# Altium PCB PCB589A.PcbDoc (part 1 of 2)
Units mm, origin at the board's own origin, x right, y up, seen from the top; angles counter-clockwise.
Board outline 111 x 86 mm, 2 copper layers (Top Layer, Top, Bottom Layer, Bottom); 127 components, 84 nets, 406 pads, 157 vias.
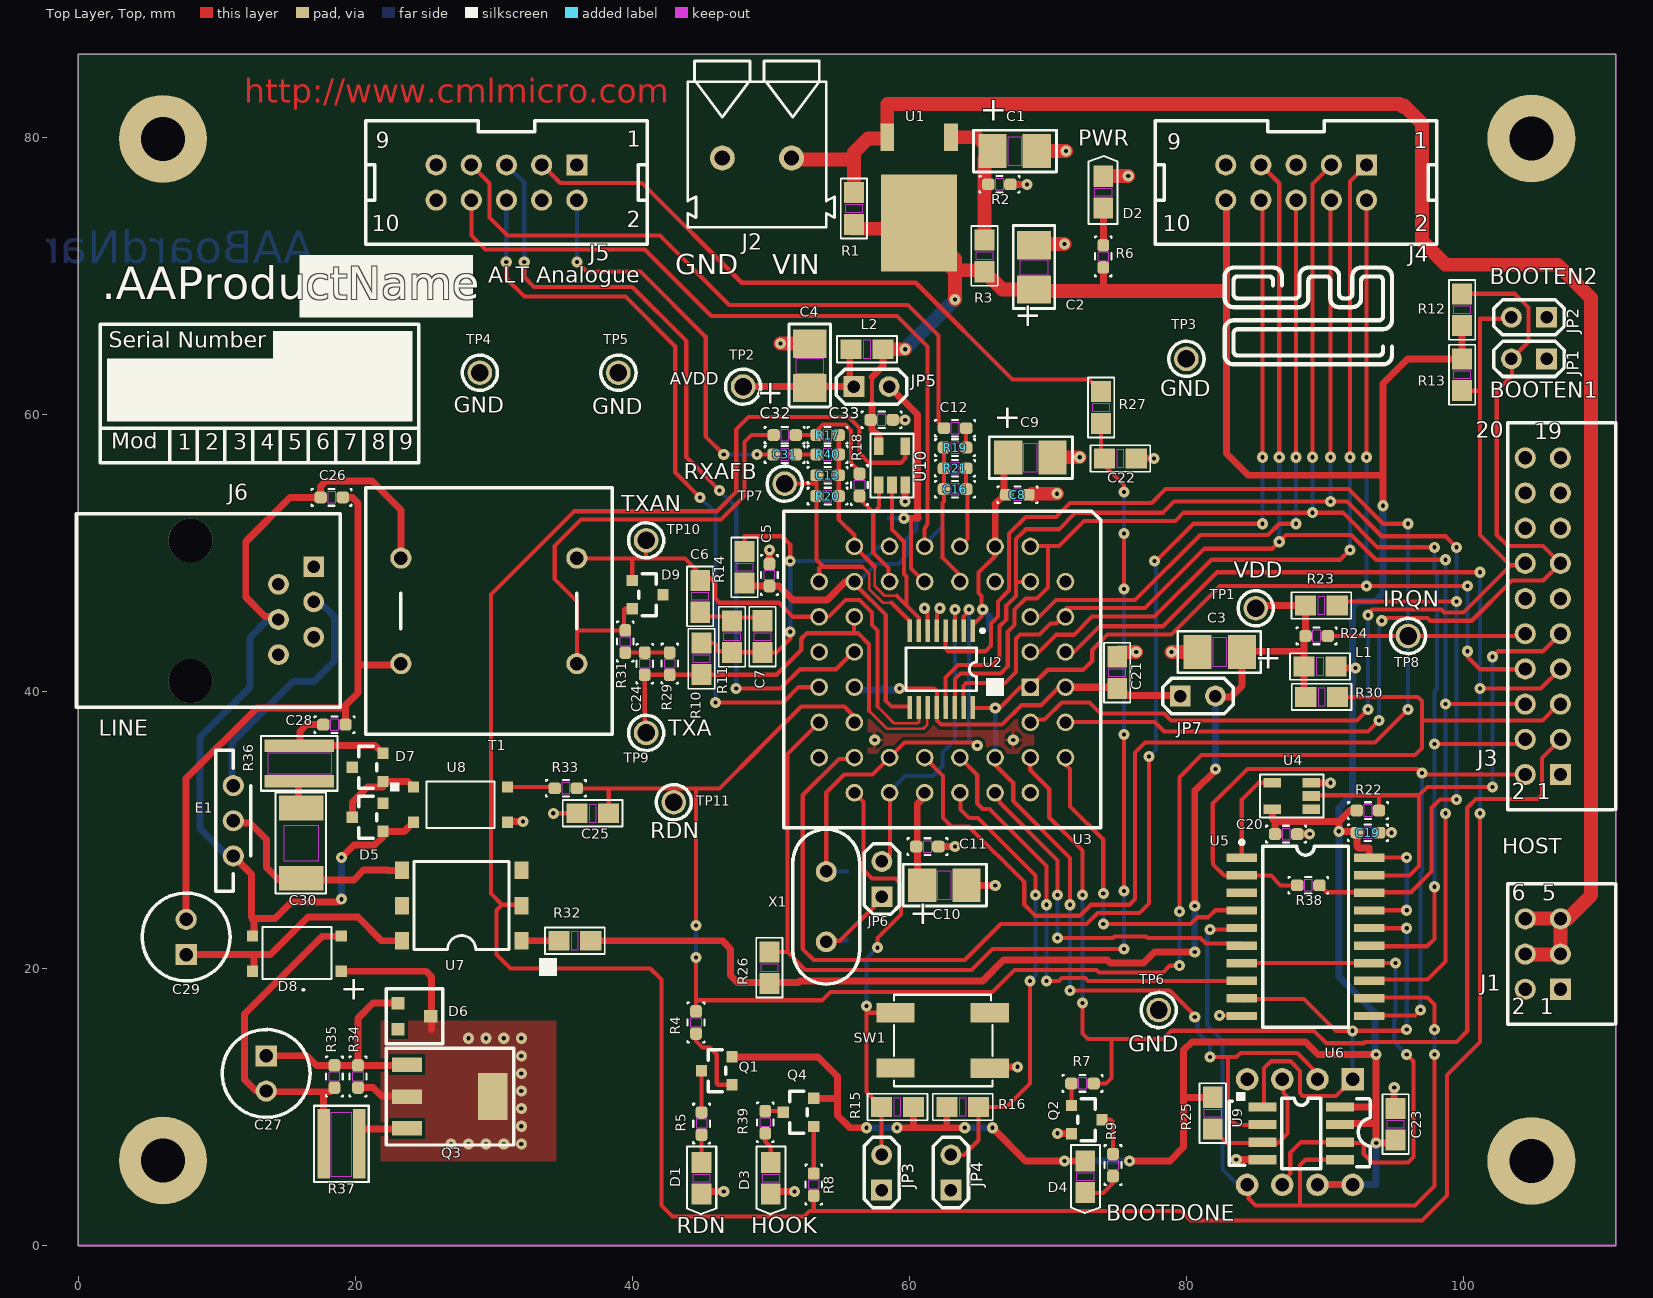
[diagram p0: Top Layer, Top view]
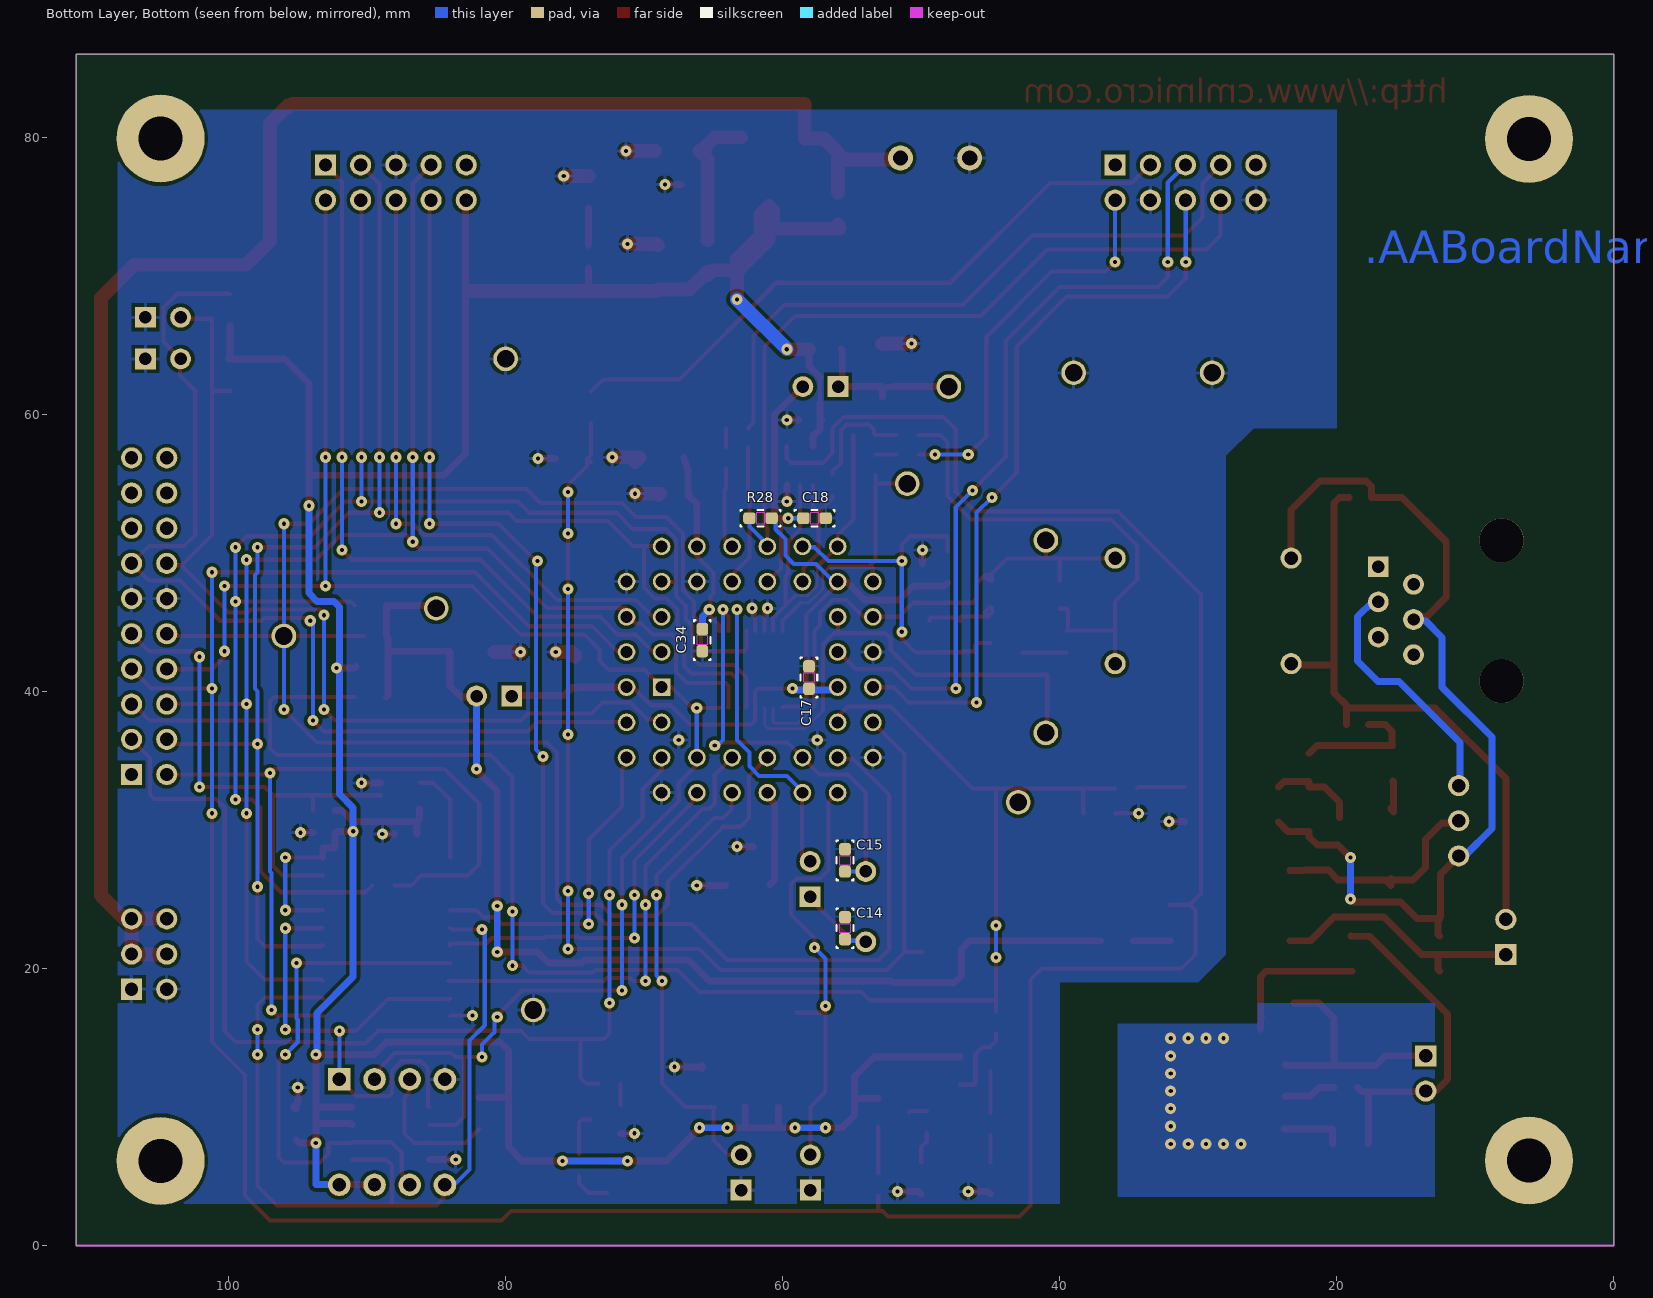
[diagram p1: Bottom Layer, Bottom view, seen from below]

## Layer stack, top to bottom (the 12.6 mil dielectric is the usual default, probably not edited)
Top Layer, Top: signal copper 0.0356
Dielectric: dielectric 0.32, FR-4, Dk 4.8
Bottom Layer, Bottom: signal copper 0.0356

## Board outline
0,0 111,0 111,86 0,86

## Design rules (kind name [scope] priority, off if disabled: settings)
Clearance Clearance_Polygon [InPolygon] p1: gap=0.25
Clearance Clearance_NetClass(LINESIDE)-NetClass(EQPTSIDE-AN) [InNetClass('LINESIDE') vs InNetClass('EQPTSIDE-AN')] p2: gap=2.5
Clearance Clearance_NetClass(LINESIDE)-NetClass(EQPTSIDE-DIG) [InNetClass('LINESIDE') vs InNetClass('EQPTSIDE-DIG')] p3: gap=2.5
Clearance Clearance_NetClass(LINESIDE) [InNetClass('LINESIDE') vs not IsKeepOut] p4: gap=0.5
Clearance Clearance_Keepout_NetClass(LINESIDE) [InNetClass('LINESIDE') vs IsKeepOut] p5: gap=0.01
Clearance "Clearance_Cu, PadToPad" [OnCopper And IsPad vs OnCopper And IsPad] p6: gap=0.2
Clearance "Clearance_Cu PadToLine" [OnCopper And IsPad vs OnCopper And IsWire] p7: gap=0.2
Clearance "Clearance_Cu, LineToLine" [OnCopper And IsWire vs OnCopper And IsWire] p8: gap=0.2
Clearance "Clearance_Cu, ViaToPad" [OnCopper And IsVia vs OnCopper And IsPad] p9: gap=0.2
Clearance "Clearance_Cu, ViaToLine" [OnCopper And IsVia vs OnCopper And IsWire] p10: gap=0.2
Clearance "Clearance_Cu, ViaToVia" [OnCopper And IsVia vs OnCopper And IsVia] p11: gap=0.2
ComponentClearance [All] p1 off: gap=0.254 collisioncheckmode=3 verticalgap=0.254 showdistances=FALSE
Height [All] p1 off: minheight=0 maxheight=25.4 prefheight=12.7
HoleSize [All] p1: absolutevalues=TRUE maxlimit=4 minlimit=0.2 maxpercent=80.000 minpercent=20.000
MinimumSolderMaskSliver [All] p1: minsoldermaskwidth=0.1
PlaneClearance [All] p1: clearance=0.254
PolygonConnect PolygonConnect_11 [All vs IsNamedPolygon('Top Layer, Top-LNET320') Or  IsNamedPolygon('Bottom Layer, Bottom-LNET320')] p1: connectstyle=Direct reliefconductorwidth=0.254 reliefentries=4 polygonreliefangle="90 Angle"
PolygonConnect PolygonConnect_10 [All vs IsNamedPolygon('Bottom Layer, Bottom-GND')] p2: connectstyle=Relief reliefconductorwidth=0.254 reliefentries=4 polygonreliefangle="90 Angle"
PolygonConnect PolygonConnect_9 [All vs IsNamedPolygon('Bottom Layer, Bottom-LNET320')] p3: connectstyle=Direct reliefconductorwidth=0.254 reliefentries=4 polygonreliefangle="90 Angle"
PolygonConnect PolygonConnect_8 [All vs IsNamedPolygon('Top Layer, Top-LNET320')] p4: connectstyle=Direct reliefconductorwidth=0.254 reliefentries=4 polygonreliefangle="90 Angle"
PolygonConnect PolygonConnect_7 [All vs IsNamedPolygon('Top Layer, Top-LNET320')] p5: connectstyle=Direct reliefconductorwidth=0.254 reliefentries=4 polygonreliefangle="90 Angle"
PolygonConnect PolygonConnect_6 [IsPolygon And InNet('GND') And OnLayer('Bottom Layer, Bottom') vs IsVia] p6: connectstyle=Relief reliefconductorwidth=0.381 reliefentries=4 polygonreliefangle="45 Angle"
PolygonConnect PolygonConnect_5 [IsPolygon And InNet('GND') And OnLayer('Bottom Layer, Bottom') vs IsPad] p7: connectstyle=Relief reliefconductorwidth=0.381 reliefentries=4 polygonreliefangle="45 Angle"
PolygonConnect PolygonConnect_4 [IsPolygon And InNet('LNET320') And OnLayer('Bottom Layer, Bottom') vs IsVia] p8: connectstyle=Direct reliefconductorwidth=0.381 reliefentries=4 polygonreliefangle="90 Angle"
PolygonConnect PolygonConnect_3 [IsPolygon And InNet('LNET320') And OnLayer('Bottom Layer, Bottom') vs IsPad] p9: connectstyle=Direct reliefconductorwidth=0.381 reliefentries=4 polygonreliefangle="90 Angle"
PolygonConnect PolygonConnect_2 [IsPolygon And InNet('LNET320') And OnLayer('Top Layer, Top') vs IsVia] p10: connectstyle=Direct reliefconductorwidth=0.381 reliefentries=4 polygonreliefangle="90 Angle"
PolygonConnect PolygonConnect_1 [IsPolygon And InNet('LNET320') And OnLayer('Top Layer, Top') vs IsPad] p11: connectstyle=Direct reliefconductorwidth=0.381 reliefentries=4 polygonreliefangle="90 Angle"
PolygonConnect [All] p12: connectstyle=Relief reliefconductorwidth=0.254 reliefentries=4 polygonreliefangle="90 Angle"
RoutingVias [All] p1: holewidth=0.5 width=1 viastyle="Through Hole" minholewidth=0.3 minwidth=0.8 maxholewidth=0.6 maxwidth=1.2
SilkToSilkClearance [All] p1: silktosilkclearance=0.15
SilkscreenOverComponentPads [All] p1: minsilkscreentomaskgap=0.1
SolderMaskExpansion [All] p1 off: expansion=0.102
UnConnectedPin [All] p1:
Width Width_LineSide [InNetClass('LINESIDE')] p1: maxlimit=0.505 minlimit=0.495 preferedwidth=0.5 minimp=50.000000 maximp=50.000000 favimp=50.000000
Width [All] p2: maxlimit=1 minlimit=0.2 preferedwidth=0.3 minimp=50.000000 maximp=50.000000 favimp=50.000000
21 further rules are at their usual default settings.

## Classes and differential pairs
net class EQPTSIDE-DIG: BOOTDONE BOOTEN1 BOOTEN2 C.CSN C.CTSN C.DCDN C.DSRN C.DVDDI C.VDD CDATA CSN EP.EPCSN EP.EPSCLK EP.EPSI EP.WPN EPCSN EPSCLK EPSI EVAL EXTLINK45 GND HDN IRQN MEMPROGN NET00000 NET00002 NET00004 NET00005 NET00006 NetC1_A NetC10_A NetC14_2 NetD1_1 NetD2_1 NetD3_1 NetQ1_1 NetQ1_3 NetQ4_1 NetQ4_3 NetR32_2 NetR33_2 RDATA RDN RLYDRV SCLK VDD VDEC VIN XTAL XTALN
net class EQPTSIDE-AN: C.AVDD C.AVDD.I NET00027 NET00028 NET00155 NET00156 NET00157 NetC24_2 NetC31_1 NetC32_2 RXA RXAFB RXAIN RXALT RXAN RXB RXBIN TXA TXAN TXB TXBN VBIAS
net class LINESIDE: NetC26_1 NetC26_2 NetC27_1 NetC27_2 NetC28_2 NetC29_2 NetC30_1 NetC30_2 NetD5_3 NetD6_3 NetE1_1 NetQ3_3

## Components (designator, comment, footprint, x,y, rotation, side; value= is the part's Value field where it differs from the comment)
C1 "n/f" TC3528P_CAP_TANT_TAJ_B(Primary) 66,79 r0 top
C2 "10uF(16V)" TC3528P_CAP_TANT_TAJ_B(Primary) 69,69 r90 top
C3 "10uF(16V)" TC3528P_CAP_TANT_TAJ_B(Primary) 84,42.84 r180 top
C4 "10uF(16V)" TC3528P_CAP_TANT_TAJ_B(Primary) 52.805,61.89 r90 top
C5 "100nF" 0603COM#1 49.9,49.2 r90 top
C6 "nf" CC0805 44.9,48 r270 top
C7 "nf" CC0805 49.4,45.1 r270 top
C8 "1uF" 0603COM#1 68.6,54.2 r0 top
C9 "10uF" TC3528P_CAP_TANT_TAJ_B(Primary) 67.14,56.874 r0 top
C10 "10uF" TC3528P_CAP_TANT_TAJ_B(Primary) 60.93,26.014 r0 top
C11 "100nF" 0603COM#1 62.1,28.8 r0 top
C12 "100nF" 0603COM#1 64.1,59 r0 top
C13 "220pF" 0603COM#2 54.9,55.6 r0 top
C14 "47pF" 0603COM#2 55.5,23.7 r90 bottom
C15 "47pF" 0603COM#2 55.5,28.6 r90 bottom
C16 "100pF" 0603COM#2 64.1,54.6 r0 top
C17 "100nF" 0603COM#2 58.1,41.8 r90 bottom
C18 "100nF" 0603COM#2 58.5,52.5 r0 bottom
C19 "10nF" 0603COM#2 92.3,29.8 r180 top
C20 "10nF" 0603COM#2 86.4,29.7 r180 top
C21 "100nF" CC0805 75,42.5 r270 top
C22 "n/f" CC0805 76.38,56.81 r180 top
C23 "100nF" CC0805 95.1,9.9 r270 top
C24 "15nF" 0603COM#2 40.9,41.2 r270 top
C25 "330nF" CC0805 36,31.2 r0 top
C26 "33nF" 0603COM#2 17.5,54 r180 top
C27 "4u7F (100V)" CAP100R 13.575,13.69 r270 top
C28 "100nF" 0603COM#2 19.3,37.6 r0 top
C29 "4u7F (100V)" CAP100R 7.8,21 r90 top
C30 "0.33uF (250v)" CC1812 16,26.5 r90 top
C31 "100nF" 0603COM#1 51.8,57.1 r0 top
C32 "100nF" 0603COM#1 51.8,58.5 r0 top
C33 "100nF" 0603COM#1 58.8,59.6 r0 top
C34 "n/f" 0603COM#1 65.8,42.9 r270 bottom
D1 "RDN" LED0805 45,6 r270 top
D2 "PWR" LED0805 74,74.9 r90 top
D3 "HOOK" LED0805 50,6 r270 top
D4 "BOOTDONE" LED0805 72.7,6.1 r270 top
D5 "n/f" SOT23(SDG) 22,29.9 r90 top
D6 "8V2" SO-G3/Z3.3 23.1,17.5 r270 top
D7 "18v" SOT23(SDG) 22,33.5 r90 top
D8 "" SDIP4 19,19.8 r180 top
D9 "2V7" SOT23(SDG) 40,48 r270 top
E1 "TM2P-10271" TM2PRO 11.2,33.2 r180 top
J1 "" IDC6RM 107,18.5 r90 top locked
J2 "SCRWLESS2" SCRWLESS_2 46.5,78.5 r90 top
J3 "HOST" IDC20RM 107,34 r90 top locked
J4 "n/f" IDC10M 93,78 r0 top
J5 "ALT Analogue" IDC10M 36,78 r0 top
J6 "LINE" RJ11SKT_RJ11SKT(Primary) 17,49 r270 top
JP1 "BOOTEN1" JMP2 106,64 r180 top
JP2 "BOOTEN2" JMP2 106,67 r180 top
JP3 "EVAL" JMP2 58,4 r90 top
JP4 "EXTLINK45" JMP2 63,4 r90 top
JP5 "JUMPER2" JMP2 56,62 r0 top
JP6 "" JMP2 58.02,25.184 r90 top
JP7 "" JMP2 79.555,39.665 r0 top
L1 "100nH" RC0805 88.5,41.8 r0 top
L2 "100nH" RC0805 55.8,64.7 r0 top
Q1 "" SOT-23 47.2,11.6 r90 top
Q2 "" SOT23(SDG)_BC846(Primary) 71.7,10.1 r270 top
Q3 "" DSO-G3/D7 23.735,13.055 r270 top
Q4 "" SOT-23 53.1,8.6 r90 top
R1 "n/f" RC0805 56,76 r270 top
R2 "0R" 0603COM#1 67.3,76.6 r0 top
R3 "n/f" RC0805 65.425,72.575 r270 top
R4 "10k" 0603COM#2 44.6,16.9 r90 top
R5 "360R" 0603COM#2 45,8 r270 top
R6 "470R" 0603COM#2 74,72.2 r90 top
R7 "10k" 0603COM#2 73.3,11.7 r0 top
R8 "10k" 0603COM#2 53.1,3.6 r270 top
R9 "360R" 0603COM#2 74.7,6.6 r90 top
R10 "nf" RC0805 45,43.5 r270 top
R11 "nf" RC0805 47.2,42.8 r90 top
R12 "10k" RC0805 99.9,66.4 r90 top
R13 "10k" RC0805 99.9,64 r270 top
R14 "0R" RC0805 48.1,50.1 r270 top
R15 "10k" RC0805 58,10 r0 top
R16 "n/f" RC0805 65,10 r180 top
R17 "150K" 0603COM#2 53.3,58.5 r180 top
R18 "27k" 0603COM#1 56.4,55.7 r90 top
R19 "150K" 0603COM#1 64.1,57.6 r0 top
R20 "100K" 0603COM#1 54.9,54.1 r0 top
R21 "150K" 0603COM#1 62.5,56.1 r180 top
R22 "10k" 0603COM#2 93.9,31.4 r0 top
R23 "1M" RC0805 88.6,46.2 r0 top
R24 "100K" 0603COM#1 88.6,44 r180 top
R25 "10k" RC0805 81.9,10.7 r270 top
R26 "470K" RC0805 49.9,21.2 r270 top
R27 "n/f" RC0805 73.84,59.35 r90 top
R28 "0R" 0603COM#2 62.4,52.5 r0 bottom
R29 "510R" 0603COM#2 42.7,42.8 r90 top
R30 "470K" RC0805 90.9,39.6 r180 top
R31 "0R" 0603COM#1 39.5,44.4 r90 top
R32 "270R" RC0805 37,22 r180 top
R33 "100R" 0603COM#2 36,33 r0 top
R34 "33K" 0603COM#2 20.2,13 r90 top
R35 "27K" 0603COM#2 18.5,13 r90 top
R36 "10k (0.5W)" RC12181WA 16,36 r270 top
R37 "22R (1W)" RC12181WA 20.2,7.3 r180 top
R38 "n/f" 0603COM#2 88,26 r180 top
R39 "360R" 0603COM#2 49.6,8.1 r270 top
R40 "150K" 0603COM#1 53.3,57.1 r180 top
SW1 "n/f" OMRONB3SN 59,16.8 r270 top
T1 "P5100" LINEXFMR_XFMR_LINE(Primary) 36,42 r180 top
TP1 "VDD" FISH_BEAD_FOOT_FISH_BEAD(Primary) 85,46 r270 top
TP2 "AVDD" FISH_BEAD_FOOT_FISH_BEAD(Primary) 48,62 r270 top
TP3 "GND" FISH_BEAD_FOOT_FISH_BEAD(Primary) 80,64 r0 top
TP4 "GND" FISH_BEAD_FOOT_FISH_BEAD(Primary) 29,63 r0 top
TP5 "GND" FISH_BEAD_FOOT_FISH_BEAD(Primary) 39,63 r0 top
TP6 "GND" FISH_BEAD_FOOT_FISH_BEAD(Primary) 78,17 r0 top
TP7 "RXAFB" FISH_BEAD_FOOT_FISH_BEAD(Primary) 51,55 r180 top
TP8 "IRQN" FISH_BEAD_FOOT_FISH_BEAD(Primary) 96,44 r0 top
TP9 "TXA" FISH_BEAD_FOOT_FISH_BEAD(Primary) 41,37 r180 top
TP10 "TXAN" FISH_BEAD_FOOT_FISH_BEAD(Primary) 41,50.9 r180 top
TP11 "RDN" FISH_BEAD_FOOT_FISH_BEAD(Primary) 43,32 r180 top
U1 "" TO-252 63,80 r180 top
U2 "CMX865AE4" E4 62.3,41.6 r180 top
U3 "" PLCCSOCKET44 68.73,40.304 r180 top
U4 "" SOT23-5 89,31.5 r90 top
U5 "" SO-G20 84,28 r0 top
U6 "" DIP8 92,12 r270 top
U7 "" SMD6 32,22 r180 top
U8 "" SOP4 24.2,33.1 r0 top
U9 "n/f" SO8 85.5,10 r0 top
U10 "TS12A4514DBVR" SOT23-5 57.8,54.9 r0 top
X1 "6.1440MHz" HC49 54,27 r270 top

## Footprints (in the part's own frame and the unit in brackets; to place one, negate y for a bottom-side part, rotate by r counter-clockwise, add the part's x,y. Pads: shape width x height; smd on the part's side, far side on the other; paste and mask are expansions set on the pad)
0603COM#1 [mm]
  rrect50% 0.9x0.85 smd: 1(0,0) 2(-1.6,0)
  Top Layer, Top keep-out region: -1.1,-0.4 -0.5,-0.4 -0.5,0.4 -1.1,0.4
  silkscreen extent -2.23,-0.6 0.64,0.6
0603COM#2 [mm]
  rrect50% 0.9x0.85 smd: 1(0,0) 2(-1.6,0)
  Top Layer, Top pour cut-out: -0.05,0.65 -1.55,0.65 -1.55,-0.65 -0.05,-0.65
  Top Layer, Top keep-out region: -1.1,-0.4 -0.5,-0.4 -0.5,0.4 -1.1,0.4
  silkscreen extent -2.23,-0.6 0.64,0.6
CAP100R [mil]
  round 60 hole 38: 1(100,0)
  rect 60x60 hole 38: 2(0,0)
  silkscreen extent -75,-125 175,125
CC0805 [mil]
  rect 60x56 smd: 1(0,0) 2(90,0)
  Top Layer, Top keep-out region: 55,-25 55,25 35,25 35,-25
  silkscreen extent -40,-38 130,38
CC1812 [mil]
  rect 70x126 smd: 1(0,-3.94) 2(200,-3.94)
  Top Layer, Top keep-out region: 150,-53.94 150,46.06 50,46.06 50,-53.94
  silkscreen extent -43,-75 244,69
DIP8 [mil]
  rect 64x64 hole 38: 1(0,0)
  round 64 hole 38: 2(0,-100) 3(0,-200) 4(0,-300) 5(300,-300) 6(300,-200) 7(300,-100) 8(300,0)
  silkscreen extent 60,-350 244,50
DSO-G3/D7 [mm]
  rect 1.05x2.15 smd: 1(0,0) 2(2.3,0) 3(4.6,0)
  rect 3.4x2.15 smd: 4(2.3,6.2)
  silkscreen extent -1.2,-1.5 5.8,7.7
E4 [mm]
  rect 0.3x1.65 smd: 1(-2.275,-2.775) 2(-1.625,-2.775) 3(-0.975,-2.775) 4(-0.325,-2.775) 5(0.325,-2.775) 6(0.975,-2.775) 7(1.625,-2.775) 8(2.275,-2.775) 9(2.275,2.775) 10(1.625,2.775) 11(0.975,2.775) 12(0.325,2.775) 13(-0.325,2.775) 14(-0.975,2.775) 15(-1.625,2.775) 16(-2.275,2.775)
  silkscreen extent -3.1,-2.9 2.55,1.55
FISH_BEAD_FOOT_FISH_BEAD(Primary) [mil]
  round 70 hole 50: TP(0,0)
  silkscreen extent -50,-50 50,50
HC49 [mm]
  round 1.5 hole 0.9: 1(0,0) 2(5.08,0)
  silkscreen extent -3.05,-2.41 8.13,2.41
IDC6RM [mil]
  rect 60x60 hole 38: 1(0,0)
  round 60 hole 38: 2(0,100) 3(100,0) 4(100,100) 5(200,0) 6(200,100)
  silkscreen extent -100,-157 300,150
IDC10M [mil]
  rect 60x60 hole 38: 1(0,0)
  round 60 hole 38: 2(0,-100) 3(-100,0) 4(-100,-100) 5(-200,0) 6(-200,-100) 7(-300,0) 8(-300,-100) 9(-400,0) 10(-400,-100)
  silkscreen extent -600,-225 200,125
IDC20RM [mil]
  rect 60x60 hole 38: 1(0,0)
  round 60 hole 38: 2(0,100) 3(100,0) 4(100,100) 5(200,0) 6(200,100) 7(300,0) 8(300,100) 9(400,0) 10(400,100) 11(500,0) 12(500,100) 13(600,0) 14(600,100) 15(700,0) 16(700,100) 17(800,0) 18(800,100) 19(900,0) 20(900,100)
  silkscreen extent -100,-157 1000,150
JMP2 [mm]
  rect 1.5x1.5 hole 0.9: 1(0,0)
  round 1.5 hole 0.9: 2(2.54,0)
  silkscreen extent -1.27,-1.27 3.81,1.27
LED0805 [mil]
  rect 60x56 smd: 1(0,0) 2(90,0)
  Top Layer, Top keep-out region: 55,-25 55,25 35,25 35,-25
  silkscreen extent -46,-41 147,42
LINEXFMR_XFMR_LINE(Primary) [mil]
  round 60 hole 38: 1(0,0) 3(0,-300) 4(500,0) 6(500,-300)
  silkscreen extent -100,-500 600,200
OMRONB3SN [mm]
  rect 1.4x2.75 smd: 1(0,0) 2(3.988,0) 3(0,6.807) 4(4.013,6.807)
  silkscreen extent -1.3,-0.1 5.3,7
PLCCSOCKET44 [mil]
  rect 50x50 hole 34: 1(0,0)
  round 50 hole 34: 2(-100,-100) 3(0,-100) 4(-100,-200) 5(0,-200) 6(-100,-300) 7(0,-400) 8(0,-300) 9(100,-400) 10(100,-300) 11(200,-400) 12(200,-300) 13(300,-400) 14(300,-300) 15(400,-400) 16(400,-300) 17(500,-400) 18(600,-300) 19(500,-300) 20(600,-200) 21(500,-200) 22(600,-100) 23(500,-100) 24(600,0) 25(500,0) 26(600,100) 27(500,100) 28(600,200) 29(500,300) 30(500,200) 31(400,300) 32(400,200) 33(300,300) 34(300,200) 35(200,300) 36(200,200) 37(100,300) 38(100,200) 39(0,300) 40(-100,200) 41(0,200) 42(-100,100) 43(0,100) 44(-100,0)
  silkscreen extent -200,-500 700,400
RC0805 [mil]
  rect 60x56 smd: 1(0,0) 2(90,0)
  Top Layer, Top keep-out region: 55,-25 55,25 35,25 35,-25
  silkscreen extent -40,-38 130,38
RC12181WA [mm]
  rect 0.9x5 smd: 1(-0.08,-0.04) 2(2.47,-0.04)
  Top Layer, Top keep-out region: 1.95,-2.3 1.95,2.3 0.45,2.3 0.45,-2.3
  silkscreen extent -0.78,-2.79 3.17,2.71
RJ11SKT_RJ11SKT(Primary) [mm]
  rect 1.5x1.5 hole 0.9: 1(0,0)
  round 1.5 hole 0.9: 2(1.27,-2.54) 3(2.54,0) 4(3.81,-2.54) 5(5.08,0) 6(6.35,-2.54)
  round 3.175 hole 3.175: dummy1(8.255,-8.89) dummy2(-1.905,-8.89)
  silkscreen extent -3.81,-17.14 10.16,1.91
SCRWLESS_2 [mm]
  round 1.8 hole 1.1: 1(0,0) 2(0,-5)
  silkscreen extent -5,-8.1 7,2.5
SDIP4 [mil]
  rect 32x32 smd: 1(0.39,0) 2(0.39,-100) 3(252.36,-100) 4(252.36,0)
  silkscreen extent 28,-126 224,53
SMD6 [mil]
  rect 40x50 smd: 1(0,0) 2(0,-100) 3(0,-200) 4(340,-200) 5(340,-100) 6(340,0)
  silkscreen extent -100,-225 305,100
SO8 [mil]
  rect 80x26 smd: 1(0,0) 2(0,-50) 3(0,-100) 4(0,-150) 5(220,-150) 6(220,-100) 7(220,-50) 8(220,0)
  silkscreen extent -75,-175 165,42
SO-G3/Z3.3 [mm]
  rect 0.9x0.95 smd: 1(0,0) 2(1.9,0) 3(0.95,2.35)
  silkscreen extent -1.05,-0.87 2.95,3.23
SO-G20 [mm]
  rect 2.2x0.6 smd: 1(0,0) 2(0,-1.27) 3(0,-2.54) 4(0,-3.81) 5(0,-5.08) 6(0,-6.35) 7(0,-7.62) 8(0,-8.89) 9(0,-10.16) 10(0,-11.43) 11(9.2,-11.43) 12(9.2,-10.16) 13(9.2,-8.89) 14(9.2,-7.62) 15(9.2,-6.35) 16(9.2,-5.08) 17(9.2,-3.81) 18(9.2,-2.54) 19(9.2,-1.27) 20(9.2,0)
  silkscreen extent -0.15,-12.24 7.7,1.25
SOP4 [mil]
  rect 32x32 smd: 1(0,0) 2(0,-100) 3(267.72,-100) 4(267.72,0)
  silkscreen extent -65,-116 230,16
SOT23(SDG) [mil]
  rect 32x32 smd: 1(0,0) 2(80,0) 3(40,87)
  silkscreen extent -20,18 100,68
SOT23(SDG)_BC846(Primary) [mil]
  rect 32x32 smd: B(0,0) C(40,87) E(80,0)
  silkscreen extent -20,18 100,68
SOT23-5 [mm]
  rect 0.7x1.25 smd: 1(0,0) 2(0.95,0) 3(1.9,0) 4(1.9,2.8) 5(0,2.8)
  silkscreen extent -0.6,-0.9 2.5,3.7
SOT-23 [mil]
  rect 32x32 smd: 1(0,0) 2(80,0) 3(40,87)
  silkscreen extent -20,18 100,68
TC3528P_CAP_TANT_TAJ_B(Primary) [mil]
  rect 80x96 smd: A(0,0) B(126,0)
  Top Layer, Top keep-out region: 83,-40 83,40 43,40 43,-40
  silkscreen extent -54,-59 182,59
TM2PRO [mil]
  round 60 hole 38: 1(0,0) 2(0,100) 3(0,200)
  silkscreen extent -50,-100 50,300
TO-252 [mm]
  rect 1x2 smd: 1(0,0) 3(4.6,0)
  rect 5.5x7 smd: 2(2.3,6.2)

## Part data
C1 C2 C3 C4 C9 C10: library part CAP_TANT_TAJ_B, "TAJ series case code B, SMT tantalum"
C5 C8 C11 C12 C13 C14 C15 C16 C17 C18 C19 C20 C24 C26 C28 C31 C32 C33 C34: library part CAP0603, "SMT capacitor"
C6 C7 C21 C22 C23 C25: library part CAP0805, "SMT capacitor"
C27 C29: library part CAP100R, "Non-polarised radial capacitor 100 thou pin spacing."
C30: library part CAP1812, "Generic capacitor, surface mount 1812"
D1 D2 D3 D4: library part LED0805, "LED, 0805 surface mount"
D5: library part BAS16, "Switching diode, surface mount SOT-23"
D6: library part BZX84, "BZX series zener 300mW SMT"
D7 D9: library part CMPZDA, "Dual Zener diode, common anode, SOT-23"
D8: library part CBRHD-02, "Central Semiconductor surface mount bridge rectifier, 0.5A"
E1: library part TM2PRO, "2Pro Integrated overcurrent/overvoltage protection device"
J1: library part HEADER_2*3RM, "3 + 3 double row 0.1in header right angle"
J2: "2-way Screwless Terminal Block"
J3: library part HEADER_2*10RM, "10 + 10 double row 0.1in header right angle"
J4 J5: library part HEADER_2*5, "10 way, 0.1inch pitch header"
J6: library part RJ11SKT, "RJ11 telephone socket"
JP1 JP2 JP3 JP4 JP6 JP7: library part JUMPER2, "PIN HEADER 2X1"
JP5: "PIN HEADER 2X1"
L1 L2: library part IND0805, "SMT Inductor"
Q1 Q4: library part BC856, "General purpose transistor PNP SMT"
Q2: library part BC846, "NPN general purpose transistor"
Q3: library part CZT2000, "NPN Darlington 2W SOT223"
R1 R3 R10 R11 R12 R13 R14 R15 R16 R25: library part CRG0805, "Generic SMT resistor, 1%.0.125W."
R2 R4 R5 R6 R7 R8 R9 R17 R18 R19 R20 R21 R22 R24 R28 R29 R31 R33 R34 R35 R38 R39 R40: library part CRG0603, "Generic SMT resistor, 1%.0.1W."
R23 R30 R32: library part CRG0805, "Generic SMT resistor, 1%.0.125W, RS CRG0805 series."
R26 R27: library part CRG0805, "Generic SMT resistor, 1%.0.125W, 0805 series."
R36 R37: library part RC12181W, "Philips Components 1W, SMT 1218  resistor"
SW1: library part OMRONB3SN, "Omron B3SN series, low profile, SMT  tactile switch"
T1: library part XFMR_LINE, "600R line transformer"
TP1 TP2 TP3 TP4 TP5 TP6 TP7 TP8 TP9 TP10 TP11: library part FISH_BEAD, "Fish Beads 1.32mm PCB hole"
U1: library part LM1117-ADJ-TO-252
U2: "Telecom Signalling Device"
U3: library part PDSP2_CLCC44_J_SKT, "PDSP2 Platform for Telecoms"
U4: library part NC7SZ04M5, "Tiny Logic single Inverter"
U5: library part 74HC244_SOIC, "Octal buffer/line driver; 3-state"
U6: library part AT25HP512-10PI-2.7, "SPI Serial EEPROM 512k"
U7: library part LCA110S, "Single pole optoMOS relay"
U8: library part PC354NT, "AC input photocoupler"
U9: library part M25P10-AVMN, "SPI 1Mbit Flash low voltage"
U10: "TI, SPST, CMOS analogue switch, surface mount SOT23-5"
X1: library part XTAL-HC49, "HC49 Xtal"

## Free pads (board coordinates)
  round 6.35 hole 3.175: 4(6.123,6.135) 4(6.123,79.883) 4(104.897,6.11) 4(104.897,79.91)

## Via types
v1: diameter 0.8, hole 0.3, Top Layer, Top to Bottom Layer, Bottom, tented both sides, 154 vias
v2: diameter 0.8, hole 0.3, Top Layer, Top to Bottom Layer, Bottom, 3 vias

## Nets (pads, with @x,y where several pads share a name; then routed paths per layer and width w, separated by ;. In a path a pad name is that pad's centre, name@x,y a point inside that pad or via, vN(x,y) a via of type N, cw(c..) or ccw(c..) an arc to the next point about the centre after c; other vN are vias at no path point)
BOOTDONE: J3.3 R7.1 U3.41 | length 81.1
  Top Layer, Top w0.3: U3.41@68.73,35.224 68.73,34.324 70.1,32.954 70.1,30.9 72.5,28.5 v1(72.5,25.3) ; v1(72.5,17.5) 72.5,15.3 72.9,14.9 74.6,14.9 ; R7.1@73.3,11.7 74.2,11.7 74.6,12.1 74.6,14.9 ; 99.5,14.7 99.482,14.7 ; J3.3@107,36.54 105.66,35.2 105.66,32.56 105.333,32.233 100.907,32.233 100.272,31.598 100.272,15.49 99.482,14.7 ; 74.6,14.9 78.3,14.9 78.9,15.5 89.2,15.5 90.1,14.6 92.8,14.6 92.9,14.7 99.482,14.7
  Bottom Layer, Bottom w0.3: v1(72.5,17.5) v1(72.5,25.3)
BOOTEN1: J3.13 JP1.2 R12.2 U3.42 | length 73.5
  Top Layer, Top w0.3: U3.42@71.27,37.764 71.29,37.784 77.716,37.784 78.4,37.1 93.1,37.1 v1(93.9,37.9) ; v1(94.1,45.1) 94.1,45.2 94.2,45.3 97.4,45.3 97.6,45.1 100.6,45.1 103.5,48 105.76,48 J3.13@107,49.24 105.74,50.5 103.2,50.5 102.4,51.3 102.4,61.7 103.5,62.8 103.5,64 JP1.2@103.46,64 104.7,65.24 104.7,67.7 103.7,68.7 100.1,68.7 R12.2@99.9,68.686
  Bottom Layer, Bottom w0.3: v1(93.9,37.9) 93.9,45 94,45 v1(94.1,45.1)
BOOTEN2: J3.14 JP2.2 R13.2 U3.43 | length 68.2
  Top Layer, Top w0.3: U3.43@68.73,37.764 68.93,37.964 69.764,37.964 71,39.2 73,39.2 73.8,38.4 78.4,38.4 78.9,37.9 92.3,37.9 v1(93.1,38.7) ; v1(93.1,45.5) 93,45.5 93.05,45.55 93.4,45.9 98.4,45.9 98.6,45.7 100,45.7 103.4,49.1 ; R13.2@99.9,61.714 99.9,61.7 101.2,61.7 ; JP2.2@103.46,67 103.36,66.9 101.2,66.9 101.2,61.7 ; J3.14@104.46,49.24 104.32,49.1 103.4,49.1 ; 101.2,61.7 101.2,51.3 103.4,49.1
  Bottom Layer, Bottom w0.3: v1(93.1,38.7) v1(93.1,45.5)
C.AVDD: C4.A JP5.1 L2.1 TP2.TP | length 11.4
  Top Layer, Top w0.5: TP2.TP@48,62 52,62 C4.A@52.805,61.89 ; C4.A@52.805,61.255 C4.A@52.805,61.89 ; L2.1@55.8,64.7 55.7,64.6 JP5.1@55.7,62 ; JP5.1@56,62 JP5.1@55.7,62 ; C4.A@52.805,61.89 52.915,62 JP5.1@55.7,62
C.AVDD.I: C18.1 JP5.2 U3.14 | length 18
  Top Layer, Top w0.3: v1@59.8,52.5 v1(59.6,52.5) 60,52.4 60.125,52.275 60.125,48.875 61,48 61.2,48 U3.14@61.11,47.924
  Top Layer, Top w0.5: JP5.2@58.54,62 60.6,60 60.6,52.5 v1@59.8,52.5
  Bottom Layer, Bottom w0.3: C18.1@58.5,52.5 v1(59.6,52.5)
C.CSN: J4.4 R23.2 R38.2 U2.13 U3.8 U5.18 | length 115.4
  Top Layer, Top w0.3: U2.13@62.625,38.825 62.6,38.85 62.6,41 63.5,41.9 66,41.9 66.5,42.4 66.5,44.7 67,45.2 67,46.2 67.7,46.9 67.7,47.9 ; U3.8@68.73,47.924 68.624,47.924 68.6,47.9 67.7,47.9 ; R38.2@89.6,26 90.1,25.5 93.2,25.5 U5.18@93.2,25.46 93.24,25.5 96.2,25.5 97.7,27 97.7,31.6 98.3,32.2 v1(99.5,32.2) ; v1(90.4,56.9) 90.4,75.4 J4.4@90.46,75.46 ; R23.2@90.886,46.2 90.986,46.3 91.186,46.5 v1(99.5,46.5) ; v1(99.5,50.4) 98.7,51.2 94.1,51.2 91.6,53.7 v1(90.4,53.7) 79.1,53.7 78.3,52.9 72,52.9 70.8,51.7 68.4,51.7 67.7,51 67.7,47.9
  Bottom Layer, Bottom w0.3: v1(90.4,53.7) v1(90.4,56.9) ; v1(99.5,32.2) v1(99.5,46.5) v1(99.5,50.4)
C.CTSN: J4.8 U3.30 | length 100.5
  Top Layer, Top w0.3: U3.30@56.03,35.224 56.03,35.124 54.924,35.124 52.3,32.5 52.3,21.4 53.1,20.6 64,20.6 66.6,23.2 72.8,23.2 73.6,24 76.6,24 77.3,24.7 v1(77.3,35.3) ; v1(77.7,49.4) 77.8,49.4 78,49.6 80.5,52.1 v1(85.5,52.1) ; J4.8@85.38,75.46 85.5,75.34 v1(85.5,56.9)
  Bottom Layer, Bottom w0.3: v1(77.3,35.3) 77.8,35.8 77.8,49.3 v1(77.7,49.4) v1@77.6,49.5 ; v1(85.5,52.1) v1(85.5,56.9)
C.DCDN: J4.1 U3.3 | length 54.4
  Top Layer, Top w0.3: U3.3@68.73,42.844 69.35,42.844 70.59,44.084 71.875,44.084 73.191,45.4 77.7,45.4 81.8,49.5 91.1,49.5 v1(91.8,50.2) ; v1(91.8,56.9) 91.8,76.8 J4.1@93,78
  Bottom Layer, Bottom w0.3: v1(91.8,50.2) v1(91.8,56.9)
C.DSRN: J4.6 U3.5 | length 45.3
  Top Layer, Top w0.3: U3.5@68.73,45.384 69.365,45.384 70.585,46.604 70.589,46.6 76.3,46.6 81,51.3 85.9,51.3 86.7,52.1 v1(87.9,52.1) ; v1(87.9,56.9) 87.9,75.44 J4.6@87.92,75.46
  Bottom Layer, Bottom w0.3: v1(87.9,52.1) v1(87.9,56.9)
C.DVDDI: C17.2 C21.2 JP7.1 U2.12 U3.25 U3.44 | length 31.4
  Top Layer, Top w0.3: v1(59.3,40.2) 61.8,40.2 62,40 62,38.85 U2.12@61.975,38.825 62,38.8 62,37.9 62.3,37.6 66.7,37.6 68.1,39 69.5,39 70.8,40.3 71.274,40.3 71.3,40.3 71.272,40.302 71.27,40.302 U3.44@71.25,40.304
  Top Layer, Top w0.5: U3.44@71.25,40.304 U3.44@71.27,40.304 ; C21.2@75,40.214 74.924,40.214 C21.2@74.854,40.284 ; JP7.1@79.555,39.665 79.3,39.7 75.8,39.7 75.2,40.3 74.87,40.3 C21.2@74.854,40.284 ; U3.44@71.27,40.304 71.272,40.302 71.274,40.3 71.29,40.284 C21.2@74.854,40.284 ; U3.44@71.27,40.304 74.834,40.304 C21.2@74.854,40.284
  Bottom Layer, Bottom w0.5: U3.25@56.03,40.304 56.056,40.304 56.26,40.1 58,40.1 C17.2@58.1,40.2 58.1,40.1 59.2,40.1 v1(59.3,40.2)
C.VDD: C3.A JP7.2 L1.1 R23.1 R24.1 R26.2 R30.2 R32.1 TP1.TP | length 86
  Top Layer, Top w0.5: R32.1@37,22 46.513,22 47.1,21.413 47.1,19.5 47.6,19 49.814,19 R26.2@49.9,18.914 ; v1(80.6,21.2) 77.7,21.2 76.9,20.4 74.5,20.4 74.3,20.6 66.8,20.6 65.3,19.1 52.1,19.1 52,19 R26.2@49.986,19 ; v1(80.6,24.5) 80.6,32.8 82.1,34.3 v1(82.1,34.4) ; JP7.2@82.095,39.665 82.3,39.6 83.2,39.6 84,40.4 C3.A@84,42.84 84.06,42.9 88.5,42.9 ; TP1.TP@85,46 85.2,46.2 R23.1@88.6,46.2 R24.1@88.6,44 88.5,43.9 88.5,42.9 ; R30.2@88.614,39.6 88.5,39.714 L1.1@88.5,41.8 88.5,42.9 ; R26.2@49.9,18.914 49.9,19 R26.2@49.986,19 ; R26.2@49.9,18.914 R26.2@49.986,19
  Bottom Layer, Bottom w0.5: v1(80.6,21.2) v1(80.6,24.5) ; JP7.2@82.095,39.665 82.1,39.7 v1(82.1,34.4)
CDATA: J3.4 J4.3 U2.14 U3.7 U5.15 | length 113.6
  Top Layer, Top w0.3: U2.14@63.275,38.825 63.3,38.85 63.3,40.9 63.7,41.3 66.6,41.3 67.1,41.8 67.1,44.3 67.6,44.8 67.6,45.9 68.4,46.7 69.2,46.7 70,47.5 70,50.5 ; U3.7@68.73,50.464 68.766,50.5 70,50.5 ; v1(89.1,56.9) 89.1,76.64 J4.3@90.46,78 ; U5.15@93.2,21.65 93.25,21.7 93.35,21.6 97.376,21.6 97.9,22.124 v1(97.9,25.9) ; v1(97.9,36.2) 104.12,36.2 J3.4@104.46,36.54 ; v1(97.9,50.4) 93.8,50.4 91.3,52.9 v1(89.1,52.9) 79.8,52.9 79.2,52.3 72.6,52.3 70.8,50.5 70,50.5
  Bottom Layer, Bottom w0.3: v1(89.1,52.9) v1(89.1,56.9) ; v1(97.9,25.9) v1(97.9,36.2) 97.9,40 98.1,40.2 98.1,48.4 97.9,48.6 v1(97.9,50.4)
CSN: J3.2 R38.1 U5.2 U5.11 | length 56
  Top Layer, Top w0.3: R38.1@88,26 86.8,26 86.1,26.7 84.03,26.7 U5.2@84,26.73 83.97,26.7 82.728,26.7 81.915,27.514 81.915,27.8 81.9,27.815 81.9,31.9 84.4,34.4 96.7,34.4 v1(97,34.1) 97.1,34 104.26,34 104.36,34.1 J3.2@104.46,34 ; U5.11@93.2,16.57 93.4,16.6 96.5,16.6 v1(96.9,17)
  Bottom Layer, Bottom w0.3: v1(96.9,17) 96.9,26.9 97,27 v1(97,34.1)
EP.EPCSN: U5.9 U5.16 U6.1 U9.1 | length 38.8
  Top Layer, Top w0.3: U5.9@84,17.84 U5.9@84.04,17.8 ; U9.1@85.5,10 85.6,10 85.6,12.8 86.1,13.3 87.5,13.3 88.2,12.6 88.2,11 88.4,10.8 90.8,10.8 U6.1@92,12 U6.1@92,12.1 ; 90.793,15.5 90.8,15.5 ; U5.16@93.2,22.92 93.22,22.9 v1(95.9,22.9) ; v1(95.9,15.6) 95.8,15.5 v1(92,15.5) 90.8,15.5 ; U5.9@84.04,17.8 88.5,17.8 90.8,15.5 ; U5.9@84.04,17.8 84.14,17.7 U5.9@84.04,17.8
  Bottom Layer, Bottom w0.3: U6.1@92,12 v1(92,15.5) ; v1(95.9,15.6) v1(95.9,22.9)
EP.EPSCLK: U5.7 U5.14 U6.6 U9.6 | length 38.8
  Top Layer, Top w0.3: U5.7@83.98,20.4 U5.7@84,20.38 ; U5.7@84,20.4 U5.7@84,20.38 ; U6.6@86.92,4.38 86.9,4.4 86.9,4.6 87.5,5.2 87.5,6.7 88.26,7.46 U9.6@91.088,7.46 91.088,7.412 91.1,7.4 92.7,7.4 92.8,7.3 92.8,6.6 93.4,6 96,6 96.4,6.4 96.4,13.3 v1(95.9,13.8) ; U5.14@93.2,20.4 v1(95.1,20.4) ; U5.7@84,20.38 84.02,20.4 U5.14@93.18,20.4 ; U5.14@93.18,20.4 93.2,20.4 U5.14@93.2,20.38 U5.14@93.18,20.4
  Bottom Layer, Bottom w0.3: v1(95.1,20.4) 95.1,16.4 95,16.3 95,14.7 v1(95.9,13.8)
EP.EPSI: U5.5 U5.12 U6.5 U9.5 | length 61.7
  Top Layer, Top w0.3: v1(81.7,22.8) 83.88,22.8 U5.5@84,22.92 ; U6.5@84.38,4.38 84.5,4.26 84.5,3.4 85,2.9 88.2,2.9 ; U9.5@91.088,6.19 88.59,6.19 88.2,5.8 88.2,2.9 ; U5.12@93.2,17.84 93.3,17.9 97.4,17.9 97.9,17.4 v1(97.9,15.6) ; v1(97.9,13.8) 97.9,4.3 96.5,2.9 88.2,2.9
  Bottom Layer, Bottom w0.3: v1(81.7,22.8) 81.5,22.6 81.5,15.9 82.6,14.8 82.6,5.5 83.7,4.4 84.4,4.4 U6.5@84.38,4.38 ; v1(97.9,13.8) v1(97.9,15.6)
EP.WPN: R25.2 U6.3 U9.3 | length 10.2
  Top Layer, Top w0.3: R25.2@81.9,8.414 81.9,8.4 82.9,7.4 U9.3@85.5,7.4 ; U9.3@85.5,7.46 U9.3@85.5,7.4 ; U6.3@86.92,12 87,11.92 87,11 87.3,10.7 87.3,8.1 86.6,7.4 U9.3@85.5,7.4
EPCSN: U3.40 U5.4 | length 23.6
  Top Layer, Top w0.3: U3.40@71.31,35.264 U3.40@71.27,35.224 71.27,34.73 71.6,34.4 71.6,31.7 74,29.3 v1(74,25.4) ; v1(74,23.2) 80.3,23.2 80.8,23.7 81.6,23.7 82.1,24.2 84,24.2 U5.4@84,24.19
  Bottom Layer, Bottom w0.3: v1(74,23.2) v1(74,25.4)
EPSCLK: U3.37 U5.6 | length 26.1
  Top Layer, Top w0.3: U3.37@66.19,32.684 66.5,32.374 66.5,32 70.7,27.8 v1(70.7,25.3) ; v1(70.7,22.2) 74.7,22.2 74.8,22.3 77.1,22.3 77.2,22.2 81,22.2 81.4,21.8 84,21.8 U5.6@84,21.65
  Bottom Layer, Bottom w0.3: v1(70.7,22.2) v1(70.7,25.3)
EPSI: U3.36 U5.8 | length 33.5
  Top Layer, Top w0.3: U3.36@63.65,35.224 64.9,33.974 64.9,31.9 65.3,31.5 65.8,31.5 69.9,27.4 v1(69.9,24.6) ; v1(69.9,19.1) 70.8,19.1 71,19.3 72.7,19.3 72.9,19.1 84.1,19.1 U5.8@84,19.11
  Bottom Layer, Bottom w0.3: v1(69.9,19.1) v1(69.9,24.6)
EVAL: JP3.2 R15.1 SW1.1 U3.29 | length 32.1
  Top Layer, Top w0.3: U3.29@56.03,32.684 56.7,32.014 56.7,27.1 57.3,26.5 59,26.5 59.4,26.1 59.4,23.9 57.7,22.2 v1(57.7,21.5) ; v1(56.9,17.3) 56.9,16.8 ; JP3.2@58,6.54 R15.1@58,10 56.9,11.1 56.9,16.8 ; SW1.1@59,16.8 56.9,16.8
  Bottom Layer, Bottom w0.3: v1(56.9,17.3) 56.9,20.7 v1(57.7,21.5)
EXTLINK45: JP4.2 R16.1 U3.35 | length 33.2
  Top Layer, Top w0.3: JP4.2@63,6.54 63.94,6.54 65,7.6 65,9.9 64.9,10 R16.1@65,10 67,10 68.7,11.7 v1(68.7,19.1) ; U3.35@63.65,32.684 63.69,32.644 63.69,31.484 64.32,30.854 64.95,30.854 69.1,26.704 v1(69.1,25.3)
  Bottom Layer, Bottom w0.3: v1(68.7,19.1) 69.1,19.5 v1(69.1,25.3)
GND: C1.B C2.B C3.B C4.B C5.1 C8.1 C9.B C10.B C11.1 C14.1 C15.1 C17.1 C18.2 C19.2 C20.2 C21.1 C22.1 C23.1 C25.1 C33.1 C34.1 D1.2 D2.2 D3.2 J1.1 J1.2 J2.1 J3.11 J3.12 J4.5 J5.4 J5.10 JP1.1 JP2.1 JP3.1 JP4.1 Q2.E R2.1 SW1.4 TP3.TP TP4.TP TP5.TP TP6.TP U2.5 U2.6 U3.6 U3.10 U3.22 U3.28 U3.39 U4.3 U5.10 U6.4 U8.3 U9.4 U10.3 | length 46.9
  Top Layer, Top w0.3: v1(34.3,31.2) C25.1@36,31.2 ; v1(61.1,46) 61.3,46 61.3,44.4 U2.6@61.325,44.375 ; U2.5@61.975,44.375 62,44.4 62,46 v1(62.2,46) ; v1(82.4,16.6) 83.97,16.6 U5.10@84,16.57
  Top Layer, Top w0.5: U8.3@31,30.56 31.04,30.6 v1(32.1,30.6) ; D1.2@45,3.714 45.186,3.9 v1(46.6,3.9) ; C5.1@49.9,49.2 v1(49.9,50.2) ; D3.2@50,3.714 50.186,3.9 v1(51.7,3.9) ; C33.1@58.8,59.6 v1(59.7,59.6) ; v1(59.7,53.7) U10.3@59.7,54.9 ; C11.1@62.1,28.8 v1(63.3,28.8) ; C10.B@64.13,26.014 64.144,26 v1(66.2,26) ; SW1.4@65.807,12.787 65.807,12.987 65.82,13 65.92,12.9 v1(67.8,12.9) ; R2.1@67.3,76.6 v1(68.5,76.6) ; v1(70.7,8.1) 71.668,8.1 Q2.E@71.7,8.068 ; C22.1@76.38,56.81 v1(77.65,56.81) ; v1(83.6,6.2) 85.49,6.2 U9.4@85.5,6.19 ; C20.2@88,29.7 v1(88.9,29.7) ; U4.3@89,33.4 v1(90.4,33.4) ; C19.2@93.9,29.8 v1(94.8,29.8) ; v1(95,11.4) 95,10.32 95.32,10 95.22,9.9 C23.1@95.1,9.9
  Top Layer, Top w1: v1(50.7,65.1) 52.795,65.1 C4.B@52.805,65.09 C4.B@52.83,65.065 ; C8.1@69,54.2 68.936,54.2 68.866,54.27 v1(70.665,54.27) ; C2.B@69,72.2 69.1,72.3 v1(71.2,72.3) ; C1.B@69.2,79 v1(71.3,79) ; C9.B@70.665,56.549 C9.B@70.34,56.874 70.366,56.9 v1(72.3,56.9) ; D2.2@74,77.186 74.014,77.2 v1(75.8,77.2) ; C21.1@75,42.5 75,42.624 75.216,42.84 v1(76.38,42.84) ; v1(78.92,42.84) C3.B@80.8,42.84
  Bottom Layer, Bottom w0.5: v1(67.8,12.9) v1@67.8,13 ; v1@94.7,29.8 v1(94.8,29.8)
  other v1: 57.5,36.5 67.5,36.5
